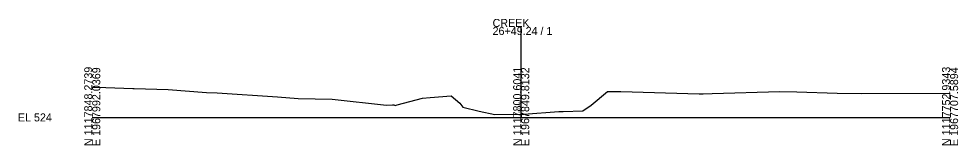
# Model space of a CAD drawing. Extents: x 9974 to 10303, y 9990 to 19550.
# Drawn here: x 9974.3 to 10302.8, y 16490.3 to 16534.4 of the extents above; entities that cross this region are included whole.
import ezdxf

# ---------------------------------------------------------------- set-up
doc = ezdxf.new("R2010")
doc.units = 0
for name, color, linetype in [('Level 10', 7, 'Continuous'), ('Level 60', 7, 'Continuous'), ('Level 63', 7, 'Continuous')]:
    doc.layers.add(name, color=color, linetype=linetype)

msp = doc.modelspace()

# ---------------------------------------------------------------- linework, layer by layer
at = {"layer": 'Level 60'}
for p, q in [((10000, 16510.52), (10000.95, 16510.52)), ((10000.95, 16510.52), (10004.74, 16510.43)), ((10004.74, 16510.43), (10014.22, 16510.14)), ((10014.22, 16510.14), (10014.62, 16510.13)), ((10014.62, 16510.13), (10026.57, 16509.75)), ((10026.57, 16509.75), (10039.92, 16508.74)), ((10174.46, 16504.29), (10180.19, 16509.02)), ((10180.19, 16509.02), (10184.84, 16509.09)), ((10184.84, 16509.09), (10212.19, 16508.26)), ((10216.78, 16508.34), (10240.51, 16509.01)), ((10240.51, 16509.01), (10246.35, 16508.98)), ((10246.35, 16508.98), (10260.54, 16508.48)), ((10039.92, 16508.74), (10043.68, 16508.6)), ((10043.68, 16508.6), (10064.84, 16507.19)), ((10064.84, 16507.19), (10072.05, 16506.63)), ((10072.05, 16506.63), (10083.85, 16506.36)), ((10083.85, 16506.36), (10102.87, 16504.25)), ((10106.58, 16504.39), (10115.44, 16506.66)), ((10115.44, 16506.66), (10118.19, 16506.92)), ((10118.19, 16506.92), (10125.56, 16507.51)), ((10125.56, 16507.51), (10128.57, 16505.02)), ((10212.19, 16508.26), (10213.6, 16508.27)), ((10213.6, 16508.27), (10216.78, 16508.34)), ((10260.54, 16508.48), (10269.13, 16508.31)), ((10269.13, 16508.31), (10300, 16508.45)), ((10102.87, 16504.25), (10104.96, 16504.35)), ((10104.96, 16504.35), (10105.47, 16504.34)), ((10105.47, 16504.34), (10105.94, 16504.21)), ((10105.94, 16504.21), (10106.58, 16504.39)), ((10128.57, 16505.02), (10129.56, 16503.61)), ((10129.56, 16503.61), (10135.34, 16502.2)), ((10135.34, 16502.2), (10140.83, 16501)), ((10164.72, 16502.01), (10171.62, 16502.32)), ((10171.62, 16502.32), (10174.46, 16504.29)), ((10140.83, 16501), (10150, 16501.09)), ((10150, 16501.09), (10150.88, 16501.1)), ((10150.88, 16501.1), (10163.22, 16502.05)), ((10163.22, 16502.05), (10164.72, 16502.01))]:
    msp.add_line(p, q, dxfattribs=at)
at = {"layer": 'Level 63'}
for p, q in [((10150, 16500), (10150, 16531.57)), ((10000, 16500), (10150, 16500)), ((10150, 16500), (10300, 16500))]:
    msp.add_line(p, q, dxfattribs=at)

# ---------------------------------------------------------------- texts
at = {"layer": 'Level 10'}
msp.add_text('525.091', height=0.8, rotation=90, dxfattribs=at).set_placement((10149.9, 16501.59))
at = {"layer": 'Level 63'}
for s, p in [('CREEK', (10140, 16531.57)), ('26+49.24 / 1', (10140, 16528.77)), ('EL 524', (9974, 16498.6))]:
    msp.add_text(s, height=2.8, dxfattribs=at).set_placement(p)
for s, p in [('N 1117848.2739', (10000, 16490)), ('E 1967992.0369', (10002.8, 16490)), ('N 1117800.6041', (10150, 16490)), ('E 1967849.8132', (10152.8, 16490)), ('N 1117752.9343', (10300, 16490)), ('E 1967707.5894', (10302.8, 16490))]:
    msp.add_text(s, height=2.8, rotation=90, dxfattribs=at).set_placement(p)

doc.saveas('drawing.dxf')
